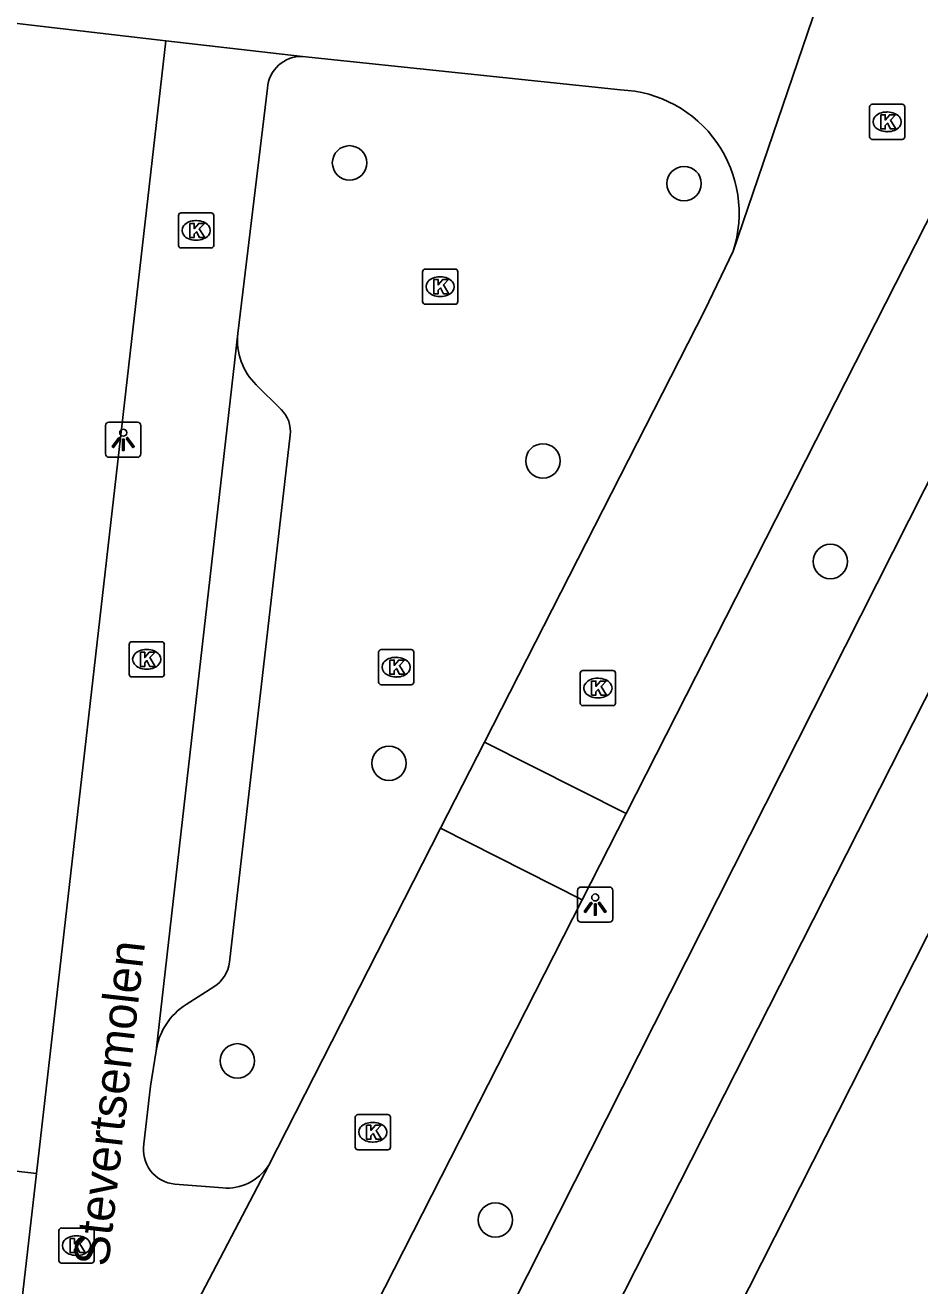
# Model space of a CAD drawing. Extents: x 161243 to 161752, y 384138 to 384885.
# Drawn here: x 161506.32 to 161531.75, y 384375.9 to 384411.76 of the extents above; entities that cross this region are included whole.
import ezdxf

# ---------------------------------------------------------------- set-up
doc = ezdxf.new("R2010")
doc.units = 0
for name, color, linetype in [('IMGEO_Boom', 7, 'Continuous'), ('IMGEO_Fietspad_gesloten', 7, 'Continuous'), ('IMGEO_Kolk', 7, 'Continuous'), ('IMGEO_Lichtpunt', 7, 'Continuous'), ('IMGEO_Openbare_ruimte_label', 7, 'Continuous'), ('IMGEO_Rijbaan_lokaal_open', 7, 'Continuous'), ('IMGEO_Voetpad_open', 7, 'Continuous')]:
    doc.layers.add(name, color=color, linetype=linetype)

msp = doc.modelspace()

# ---------------------------------------------------------------- linework, layer by layer
at = {"layer": 'IMGEO_Boom'}
for centre in [(161515.538, 384407.847), (161525.05, 384407.257), (161521.036, 384399.369), (161529.208, 384396.507), (161516.659, 384390.769), (161512.35, 384382.302), (161519.687, 384377.776)]:
    msp.add_circle(centre, 0.489, dxfattribs=at)
at = {"layer": 'IMGEO_Fietspad_gesloten'}
for points in [[(161518.014, 384365.014), (161522.72, 384374.49), (161548.308, 384424.931), (161625.518, 384576.727)], [(161520.707, 384363.649), (161526.535, 384375.146), (161550.415, 384422.299), (161627.114, 384573.143), (161627.772, 384574.506), (161627.927, 384574.874), (161628.195, 384575.423)]]:
    msp.add_lwpolyline(points, dxfattribs=at)
at = {"layer": 'IMGEO_Kolk'}
for p, q in [((161530.323, 384408.588), (161530.323, 384409.44)), ((161530.398, 384409.514), (161531.25, 384409.514)), ((161530.811, 384409.294), (161530.836, 384409.294)), ((161531.324, 384409.44), (161531.324, 384408.588)), ((161530.834, 384408.734), (161530.809, 384408.734)), ((161531.25, 384408.514), (161530.398, 384408.514)), ((161510.751, 384406.425), (161511.603, 384406.425)), ((161510.676, 384405.499), (161510.676, 384406.351)), ((161511.164, 384406.205), (161511.189, 384406.205)), ((161511.677, 384406.351), (161511.677, 384405.499)), ((161511.603, 384405.425), (161510.751, 384405.425)), ((161511.187, 384405.645), (161511.162, 384405.645)), ((161517.615, 384403.899), (161517.615, 384404.751)), ((161517.69, 384404.825), (161518.542, 384404.825)), ((161518.103, 384404.605), (161518.128, 384404.605)), ((161518.616, 384404.751), (161518.616, 384403.899)), ((161518.126, 384404.045), (161518.101, 384404.045)), ((161518.542, 384403.825), (161517.69, 384403.825)), ((161509.347, 384394.224), (161510.199, 384394.224)), ((161509.272, 384393.298), (161509.272, 384394.15)), ((161509.76, 384394.004), (161509.785, 384394.004)), ((161510.273, 384394.15), (161510.273, 384393.298)), ((161516.364, 384393.075), (161516.364, 384393.927)), ((161516.439, 384394.001), (161517.291, 384394.001)), ((161517.365, 384393.927), (161517.365, 384393.075)), ((161516.852, 384393.781), (161516.877, 384393.781)), ((161510.199, 384393.224), (161509.347, 384393.224)), ((161509.783, 384393.444), (161509.758, 384393.444)), ((161516.875, 384393.221), (161516.85, 384393.221)), ((161522.099, 384392.48), (161522.099, 384393.332)), ((161522.174, 384393.406), (161523.026, 384393.406)), ((161522.587, 384393.186), (161522.612, 384393.186)), ((161523.1, 384393.332), (161523.1, 384392.48)), ((161517.291, 384393.001), (161516.439, 384393.001)), ((161523.026, 384392.406), (161522.174, 384392.406)), ((161522.61, 384392.626), (161522.585, 384392.626)), ((161515.701, 384379.846), (161515.701, 384380.698)), ((161515.776, 384380.772), (161516.628, 384380.772)), ((161516.702, 384380.698), (161516.702, 384379.846)), ((161516.189, 384380.552), (161516.214, 384380.552)), ((161516.212, 384379.992), (161516.187, 384379.992)), ((161516.628, 384379.772), (161515.776, 384379.772)), ((161507.275, 384376.621), (161507.275, 384377.473)), ((161507.35, 384377.547), (161508.202, 384377.547)), ((161508.276, 384377.473), (161508.276, 384376.621)), ((161507.763, 384377.327), (161507.788, 384377.327)), ((161507.786, 384376.767), (161507.761, 384376.767)), ((161508.202, 384376.547), (161507.35, 384376.547))]:
    msp.add_line(p, q, dxfattribs=at)
for points in [[(161530.323, 384408.588), (161530.323, 384409.44)], [(161530.398, 384409.514), (161531.25, 384409.514)], [(161531.324, 384409.44), (161531.324, 384408.588)], [(161530.644, 384409.214), (161530.767, 384409.214), (161530.767, 384409.063), (161530.897, 384409.214), (161531.061, 384409.214), (161530.915, 384409.063), (161531.068, 384408.814), (161530.916, 384408.814), (161530.831, 384408.978), (161530.767, 384408.911), (161530.767, 384408.814), (161530.644, 384408.814), (161530.644, 384409.214)], [(161531.25, 384408.514), (161530.398, 384408.514)], [(161510.751, 384406.425), (161511.603, 384406.425)], [(161510.676, 384405.499), (161510.676, 384406.351)], [(161510.997, 384406.125), (161511.12, 384406.125), (161511.12, 384405.974), (161511.25, 384406.125), (161511.414, 384406.125), (161511.268, 384405.974), (161511.421, 384405.725), (161511.269, 384405.725), (161511.184, 384405.889), (161511.12, 384405.822), (161511.12, 384405.725), (161510.997, 384405.725), (161510.997, 384406.125)], [(161511.677, 384406.351), (161511.677, 384405.499)], [(161511.603, 384405.425), (161510.751, 384405.425)], [(161517.615, 384403.899), (161517.615, 384404.751)], [(161517.69, 384404.825), (161518.542, 384404.825)], [(161518.616, 384404.751), (161518.616, 384403.899)], [(161517.936, 384404.525), (161518.059, 384404.525), (161518.059, 384404.374), (161518.189, 384404.525), (161518.353, 384404.525), (161518.207, 384404.374), (161518.36, 384404.125), (161518.208, 384404.125), (161518.123, 384404.289), (161518.059, 384404.222), (161518.059, 384404.125), (161517.936, 384404.125), (161517.936, 384404.525)], [(161518.542, 384403.825), (161517.69, 384403.825)], [(161509.347, 384394.224), (161510.199, 384394.224)], [(161509.272, 384393.298), (161509.272, 384394.15)], [(161509.593, 384393.924), (161509.716, 384393.924), (161509.716, 384393.773), (161509.846, 384393.924), (161510.01, 384393.924), (161509.864, 384393.773), (161510.017, 384393.524), (161509.865, 384393.524), (161509.78, 384393.688), (161509.716, 384393.621), (161509.716, 384393.524), (161509.593, 384393.524), (161509.593, 384393.924)], [(161510.273, 384394.15), (161510.273, 384393.298)], [(161516.364, 384393.075), (161516.364, 384393.927)], [(161516.439, 384394.001), (161517.291, 384394.001)], [(161517.365, 384393.927), (161517.365, 384393.075)], [(161516.685, 384393.701), (161516.808, 384393.701), (161516.808, 384393.55), (161516.938, 384393.701), (161517.102, 384393.701), (161516.956, 384393.55), (161517.109, 384393.301), (161516.957, 384393.301), (161516.872, 384393.465), (161516.808, 384393.398), (161516.808, 384393.301), (161516.685, 384393.301), (161516.685, 384393.701)], [(161510.199, 384393.224), (161509.347, 384393.224)], [(161522.099, 384392.48), (161522.099, 384393.332)], [(161522.174, 384393.406), (161523.026, 384393.406)], [(161523.1, 384393.332), (161523.1, 384392.48)], [(161517.291, 384393.001), (161516.439, 384393.001)], [(161522.42, 384393.106), (161522.543, 384393.106), (161522.543, 384392.955), (161522.673, 384393.106), (161522.837, 384393.106), (161522.691, 384392.955), (161522.844, 384392.706), (161522.692, 384392.706), (161522.607, 384392.87), (161522.543, 384392.803), (161522.543, 384392.706), (161522.42, 384392.706), (161522.42, 384393.106)], [(161523.026, 384392.406), (161522.174, 384392.406)], [(161515.701, 384379.846), (161515.701, 384380.698)], [(161515.776, 384380.772), (161516.628, 384380.772)], [(161516.702, 384380.698), (161516.702, 384379.846)], [(161516.022, 384380.472), (161516.145, 384380.472), (161516.145, 384380.321), (161516.275, 384380.472), (161516.439, 384380.472), (161516.293, 384380.321), (161516.446, 384380.072), (161516.294, 384380.072), (161516.209, 384380.236), (161516.145, 384380.169), (161516.145, 384380.072), (161516.022, 384380.072), (161516.022, 384380.472)], [(161516.628, 384379.772), (161515.776, 384379.772)], [(161507.275, 384376.621), (161507.275, 384377.473)], [(161507.35, 384377.547), (161508.202, 384377.547)], [(161508.276, 384377.473), (161508.276, 384376.621)], [(161507.596, 384377.247), (161507.719, 384377.247), (161507.719, 384377.096), (161507.849, 384377.247), (161508.013, 384377.247), (161507.867, 384377.096), (161508.02, 384376.847), (161507.868, 384376.847), (161507.783, 384377.011), (161507.719, 384376.944), (161507.719, 384376.847), (161507.596, 384376.847), (161507.596, 384377.247)], [(161508.202, 384376.547), (161507.35, 384376.547)]]:
    msp.add_lwpolyline(points, dxfattribs=at)
for centre, start, end in [((161530.4, 384409.438), 91.552, 178.448), ((161530.4, 384409.438), 91.552, 178.448), ((161531.248, 384409.438), 1.552, 88.448), ((161531.248, 384409.438), 1.552, 88.448), ((161530.4, 384408.59), 181.552, 268.448), ((161530.4, 384408.59), 181.552, 268.448), ((161531.248, 384408.59), 271.552, 358.448), ((161531.248, 384408.59), 271.552, 358.448), ((161510.753, 384406.349), 91.552, 178.448), ((161510.753, 384406.349), 91.552, 178.448), ((161511.601, 384406.349), 1.552, 88.448), ((161511.601, 384406.349), 1.552, 88.448), ((161510.753, 384405.501), 181.552, 268.448), ((161510.753, 384405.501), 181.552, 268.448), ((161511.601, 384405.501), 271.552, 358.448), ((161511.601, 384405.501), 271.552, 358.448), ((161517.692, 384404.749), 91.552, 178.448), ((161517.692, 384404.749), 91.552, 178.448), ((161518.54, 384404.749), 1.552, 88.448), ((161518.54, 384404.749), 1.552, 88.448), ((161517.692, 384403.901), 181.552, 268.448), ((161517.692, 384403.901), 181.552, 268.448), ((161518.54, 384403.901), 271.552, 358.448), ((161518.54, 384403.901), 271.552, 358.448), ((161509.349, 384394.148), 91.552, 178.448), ((161509.349, 384394.148), 91.552, 178.448), ((161510.197, 384394.148), 1.552, 88.448), ((161510.197, 384394.148), 1.552, 88.448), ((161516.441, 384393.925), 91.552, 178.448), ((161516.441, 384393.925), 91.552, 178.448), ((161517.289, 384393.925), 1.552, 88.448), ((161517.289, 384393.925), 1.552, 88.448), ((161509.349, 384393.3), 181.552, 268.448), ((161509.349, 384393.3), 181.552, 268.448), ((161510.197, 384393.3), 271.552, 358.448), ((161510.197, 384393.3), 271.552, 358.448), ((161522.176, 384393.33), 91.552, 178.448), ((161522.176, 384393.33), 91.552, 178.448), ((161523.024, 384393.33), 1.552, 88.448), ((161523.024, 384393.33), 1.552, 88.448), ((161516.441, 384393.077), 181.552, 268.448), ((161516.441, 384393.077), 181.552, 268.448), ((161517.289, 384393.077), 271.552, 358.448), ((161517.289, 384393.077), 271.552, 358.448), ((161522.176, 384392.482), 181.552, 268.448), ((161522.176, 384392.482), 181.552, 268.448), ((161523.024, 384392.482), 271.552, 358.448), ((161523.024, 384392.482), 271.552, 358.448), ((161515.778, 384380.696), 91.552, 178.448), ((161515.778, 384380.696), 91.552, 178.448), ((161516.626, 384380.696), 1.552, 88.448), ((161516.626, 384380.696), 1.552, 88.448), ((161515.778, 384379.848), 181.552, 268.448), ((161515.778, 384379.848), 181.552, 268.448), ((161516.626, 384379.848), 271.552, 358.448), ((161516.626, 384379.848), 271.552, 358.448), ((161507.352, 384377.471), 91.552, 178.448), ((161507.352, 384377.471), 91.552, 178.448), ((161508.2, 384377.471), 1.552, 88.448), ((161508.2, 384377.471), 1.552, 88.448), ((161507.352, 384376.623), 181.552, 268.448), ((161507.352, 384376.623), 181.552, 268.448), ((161508.2, 384376.623), 271.552, 358.448), ((161508.2, 384376.623), 271.552, 358.448)]:
    msp.add_arc(centre, 0.0765, start, end, dxfattribs=at)
for centre, major_axis, ratio, start_param, end_param in [((161530.81, 384409.014), (-0.387, 0.002), 0.722429, 4.712389, 7.853982), ((161530.835, 384409.014), (-0.39, 0.002), 0.717154, 1.570796, 4.712389), ((161511.163, 384405.925), (-0.387, 0.002), 0.722429, 4.712389, 7.853982), ((161511.188, 384405.925), (-0.39, 0.002), 0.717154, 1.570796, 4.712389), ((161518.102, 384404.325), (-0.387, 0.002), 0.722429, 4.712389, 7.853982), ((161518.127, 384404.325), (-0.39, 0.002), 0.717154, 1.570796, 4.712389), ((161509.759, 384393.724), (-0.387, 0.002), 0.722429, 4.712389, 7.853982), ((161509.784, 384393.724), (-0.39, 0.002), 0.717154, 1.570796, 4.712389), ((161516.851, 384393.501), (-0.387, 0.002), 0.722429, 4.712389, 7.853982), ((161516.876, 384393.501), (-0.39, 0.002), 0.717154, 1.570796, 4.712389), ((161522.586, 384392.906), (-0.387, 0.002), 0.722429, 4.712389, 7.853982), ((161522.611, 384392.906), (-0.39, 0.002), 0.717154, 1.570796, 4.712389), ((161516.188, 384380.272), (-0.387, 0.002), 0.722429, 4.712389, 7.853982), ((161516.213, 384380.272), (-0.39, 0.002), 0.717154, 1.570796, 4.712389), ((161507.762, 384377.047), (-0.387, 0.002), 0.722429, 4.712389, 7.853982), ((161507.787, 384377.047), (-0.39, 0.002), 0.717154, 1.570796, 4.712389)]:
    msp.add_ellipse(centre, major_axis=major_axis, ratio=ratio, start_param=start_param, end_param=end_param, dxfattribs=at)
at = {"layer": 'IMGEO_Lichtpunt'}
for p, q in [((161508.605, 384400.373), (161508.605, 384399.566)), ((161508.605, 384400.373), (161508.605, 384399.566)), ((161509.507, 384400.468), (161508.699, 384400.468)), ((161509.507, 384400.468), (161508.699, 384400.468)), ((161509.601, 384399.566), (161509.601, 384400.373)), ((161509.601, 384399.566), (161509.601, 384400.373)), ((161508.699, 384399.472), (161509.507, 384399.472)), ((161508.699, 384399.472), (161509.507, 384399.472)), ((161522.024, 384387.151), (161522.024, 384386.344)), ((161522.024, 384387.151), (161522.024, 384386.344)), ((161522.926, 384387.246), (161522.118, 384387.246)), ((161522.926, 384387.246), (161522.118, 384387.246)), ((161523.02, 384386.344), (161523.02, 384387.151)), ((161523.02, 384386.344), (161523.02, 384387.151)), ((161522.118, 384386.25), (161522.926, 384386.25)), ((161522.118, 384386.25), (161522.926, 384386.25))]:
    msp.add_line(p, q, dxfattribs=at)
for points in [[(161508.979, 384400.037), (161509.018, 384400.009), (161508.83, 384399.747), (161508.792, 384399.774), (161508.979, 384400.037)], [(161509.081, 384399.989), (161509.128, 384399.989), (161509.128, 384399.667), (161509.081, 384399.667), (161509.081, 384399.989)], [(161509.191, 384400.009), (161509.229, 384400.036), (161509.416, 384399.774), (161509.377, 384399.746), (161509.191, 384400.009)], [(161522.398, 384386.815), (161522.437, 384386.787), (161522.249, 384386.525), (161522.211, 384386.552), (161522.398, 384386.815)], [(161522.5, 384386.767), (161522.547, 384386.767), (161522.547, 384386.445), (161522.5, 384386.445), (161522.5, 384386.767)], [(161522.61, 384386.787), (161522.648, 384386.814), (161522.835, 384386.552), (161522.796, 384386.524), (161522.61, 384386.787)]]:
    msp.add_lwpolyline(points, dxfattribs=at)
for centre in [(161509.104, 384400.171), (161522.523, 384386.949)]:
    msp.add_circle(centre, 0.0994, dxfattribs=at)
for centre, start, end in [((161508.699, 384400.373), 90, 180), ((161508.699, 384400.373), 90, 180), ((161509.507, 384400.373), 0, 90), ((161509.507, 384400.373), 0, 90), ((161508.699, 384399.566), 180, 270), ((161508.699, 384399.566), 180, 270), ((161509.507, 384399.566), 270, 0), ((161509.507, 384399.566), 270, 360), ((161522.118, 384387.151), 90, 180), ((161522.118, 384387.151), 90, 180), ((161522.926, 384387.151), 0, 90), ((161522.926, 384387.151), 0, 90), ((161522.118, 384386.344), 180, 270), ((161522.118, 384386.344), 180, 270), ((161522.926, 384386.344), 270, 0), ((161522.926, 384386.344), 270, 360)]:
    msp.add_arc(centre, 0.0946, start, end, dxfattribs=at)
at = {"layer": 'IMGEO_Rijbaan_lokaal_open'}
for points in [[(161526.445, 384405.335), (161530.396, 384416.943)], [(161510.318, 384411.321), (161500, 384412.531), (161489.559, 384413.756)], [(161534.75, 384411.657), (161523.399, 384389.338)], [(161506.638, 384379.095), (161510.318, 384411.321)], [(161510.318, 384411.321), (161514.204, 384410.875)], [(161514.204, 384410.875), (161523.243, 384409.923)], [(161512.362, 384402.988), (161513.203, 384409.97)], [(161519.378, 384391.372), (161525.642, 384403.66), (161526.445, 384405.335)], [(161510.039, 384382.583), (161512.362, 384402.988)], [(161518.129, 384388.922), (161519.378, 384391.372)], [(161519.378, 384391.372), (161523.399, 384389.338)], [(161523.399, 384389.338), (161522.153, 384386.887)], [(161513.23, 384379.318), (161518.129, 384388.922)], [(161522.153, 384386.887), (161518.129, 384388.922)], [(161512.946, 384368.783), (161514.942, 384372.709), (161522.153, 384386.887)], [(161463.961, 384384), (161506.638, 384379.095)], [(161509.691, 384379.943), (161509.881, 384381.582), (161510.039, 384382.583)], [(161510.808, 384374.674), (161513.23, 384379.318)], [(161506.195, 384375.218), (161506.638, 384379.095)], [(161511.934, 384378.685), (161510.569, 384378.795)]]:
    msp.add_lwpolyline(points, dxfattribs=at)
for centre, radius, start, end in [((161514.18, 384409.895), 0.98, 88.6249, 175.6083), ((161523.105, 384406.415), 3.51, 342.073, 87.75), ((161510.661, 384379.775), 0.984, 170.1686, 264.6495), ((161512.044, 384380.102), 1.421, 265.5446, 326.5196)]:
    msp.add_arc(centre, radius, start, end, dxfattribs=at)
at = {"layer": 'IMGEO_Voetpad_open'}
for points in [[(161537.768, 384410.079), (161536.758, 384408.103), (161532.338, 384399.452), (161516.97, 384369.014), (161516.109, 384367.226), (161512.946, 384368.783)], [(161513.593, 384400.835), (161512.887, 384401.532)], [(161512.123, 384385.108), (161513.853, 384400.098)], [(161510.896, 384383.907), (161511.683, 384384.407)]]:
    msp.add_lwpolyline(points, dxfattribs=at)
for centre, radius, start, end in [((161514.124, 384402.801), 1.772, 173.9326, 225.7237), ((161512.968, 384400.2), 0.891, 353.4064, 45.4574), ((161511.165, 384385.221), 0.965, 302.4931, 353.276), ((161511.909, 384382.312), 1.89, 122.424, 171.7476)]:
    msp.add_arc(centre, radius, start, end, dxfattribs=at)

# ---------------------------------------------------------------- texts
at = {"layer": 'IMGEO_Openbare_ruimte_label'}
msp.add_text('Stevertsemolen', height=1, rotation=83.5143, dxfattribs=at).set_placement((161508.678, 384376.428))

doc.saveas('drawing.dxf')
